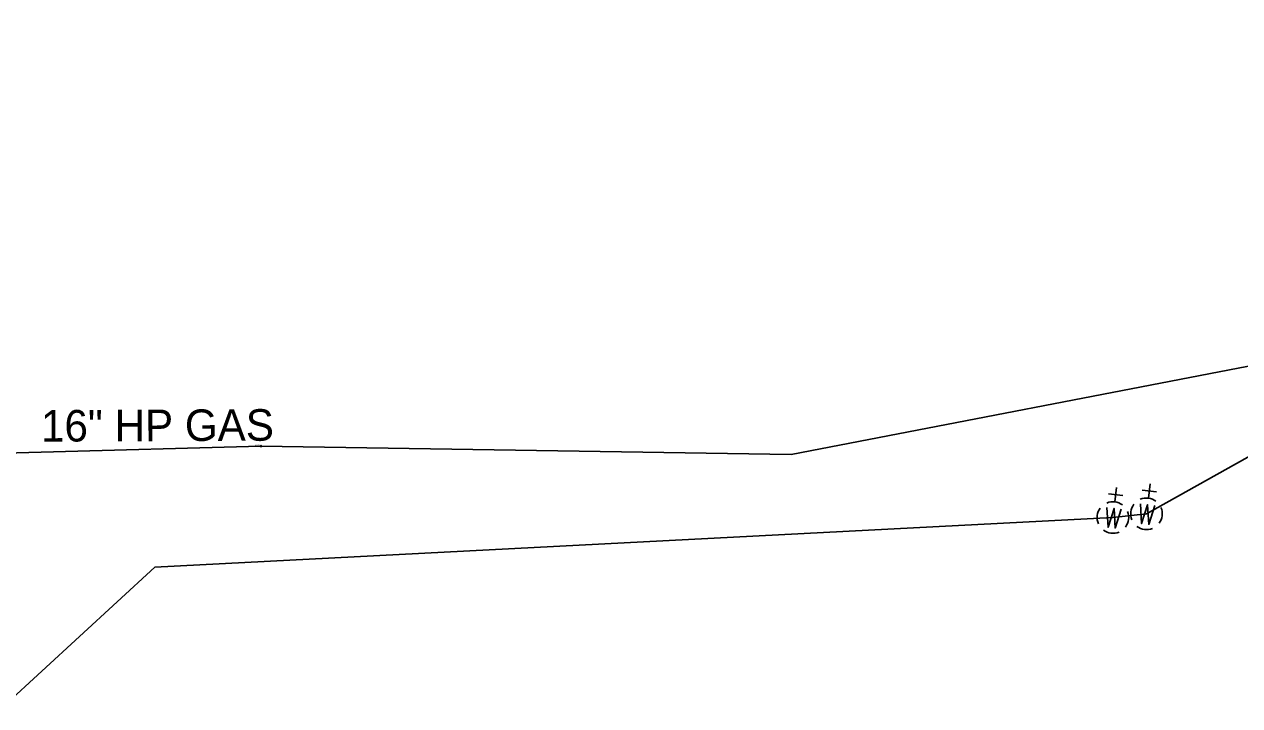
# Model space of a CAD drawing. Extents: x 1825330 to 1832613, y 710925 to 712586.
# Drawn here: x 1827544 to 1827651.9, y 711626.1 to 711686.5 of the extents above; entities that cross this region are included whole.
import ezdxf

# ---------------------------------------------------------------- set-up
doc = ezdxf.new("R2010")
doc.units = 0
for name, color, linetype in [('COC_BLD', 7, 'Continuous'), ('COC_UELC_GUY', 7, 'Continuous'), ('COC_USAN_MH', 7, 'Continuous'), ('CT-MISC-TEXT-N', 7, 'Continuous'), ('P-TEXT', 7, 'Continuous')]:
    doc.layers.add(name, color=color, linetype=linetype)

msp = doc.modelspace()

# ---------------------------------------------------------------- linework, layer by layer
at = {"layer": 'COC_UELC_GUY'}
for p, q in [((1827643.6, 711643.1), (1827663.71, 711654.32)), ((1827555.56, 711638.37), (1827640.62, 711642.77)), ((1827640.62, 711642.77), (1827643.6, 711643.1)), ((1827542.19, 711626.08), (1827555.56, 711638.37))]:
    msp.add_line(p, q, dxfattribs=at)
at = {"layer": 'COC_USAN_MH'}
for p, q in [((1827612.04, 711648.37), (1827723.98, 711669.92)), ((1827564.98, 711649.1), (1827612.04, 711648.37))]:
    msp.add_line(p, q, dxfattribs=at)
msp.add_lwpolyline([(1827446.1, 711686.52), (1827445.15, 711683.19), (1827445.37, 711681.52), (1827446.52, 711680.73), (1827484.62, 711670.58), (1827495.55, 711668.21), (1827503.96, 711666.13), (1827505.01, 711665.41), (1827505.39, 711664.49), (1827505.66, 711656.37), (1827505.74, 711649.42), (1827505.96, 711647.63), (1827507.8, 711647.37), (1827525.93, 711648.05), (1827564.98, 711649.1)], dxfattribs=at)
at = {"layer": 'CT-MISC-TEXT-N'}
for p, q in [((1827564.92, 711649.03), (1827565.05, 711649.17)), ((1827564.92, 711649.17), (1827565.05, 711649.03))]:
    msp.add_line(p, q, dxfattribs=at)
at = {"layer": 'P-TEXT'}
for p, q in [((1827640.79, 711644.16), (1827640.94, 711645.42)), ((1827643.77, 711644.49), (1827643.93, 711645.75)), ((1827641.49, 711644.71), (1827640.23, 711644.87)), ((1827644.48, 711645.04), (1827643.22, 711645.19)), ((1827640.62, 711642.77), (1827640.62, 711642.77)), ((1827643.6, 711643.1), (1827643.6, 711643.1))]:
    msp.add_line(p, q, dxfattribs=at)
for points in [[(1827640.08, 711643.66), (1827640.19, 711641.91), (1827640.72, 711643.58), (1827640.82, 711641.83), (1827641.35, 711643.5)], [(1827643.07, 711643.99), (1827643.17, 711642.24), (1827643.7, 711643.91), (1827643.81, 711642.16), (1827644.33, 711643.83)]]:
    msp.add_lwpolyline(points, dxfattribs=at)
for centre, start, end in [((1827643.6, 711643.1), 53.0068, 113.0042), ((1827640.62, 711642.77), 143.0068, 202.9701), ((1827640.62, 711642.77), 53.0068, 113.0042), ((1827640.62, 711642.77), 323.0068, 22.9701), ((1827643.6, 711643.1), 143.0068, 202.9701), ((1827643.6, 711643.1), 323.0068, 22.9701), ((1827640.62, 711642.77), 232.9727, 292.9701), ((1827643.6, 711643.1), 232.9727, 292.9701)]:
    msp.add_arc(centre, 1.4, start, end, dxfattribs=at)

# ---------------------------------------------------------------- texts
at = {"layer": 'COC_BLD'}
msp.add_text('16" HP GAS', height=2.8, rotation=0.2384, dxfattribs=at).set_placement((1827545.45, 711649.5))
at = {"layer": 'CT-MISC-TEXT-N'}
msp.add_text('30035', height=0.14, dxfattribs=at).set_placement((1827564.39, 711649.1))

doc.saveas('drawing.dxf')
